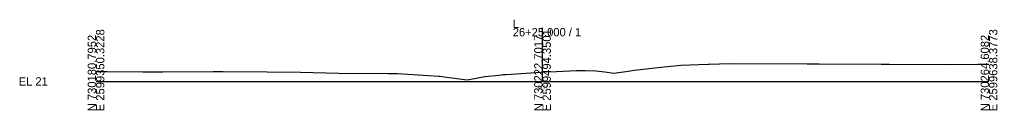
# Model space of a CAD drawing. Extents: x -26 to 3303, y -10 to 9555.
# Drawn here: x 2974.3 to 3302.8, y 2490.3 to 2520.7 of the extents above; entities that cross this region are included whole.
import ezdxf

# ---------------------------------------------------------------- set-up
doc = ezdxf.new("R2010")
doc.units = 0
for name, color, linetype in [('Exist Cross Section Cell', 7, 'Continuous'), ('Exist XS Center Line Elevation Label', 7, 'Continuous'), ('Exist XS Ground Line', 7, 'Continuous')]:
    doc.layers.add(name, color=color, linetype=linetype)

msp = doc.modelspace()

# ---------------------------------------------------------------- linework, layer by layer
at = {"layer": 'Exist Cross Section Cell'}
for p, q in [((3150, 2500), (3150, 2517.89)), ((3000, 2500), (3150, 2500)), ((3150, 2500), (3300, 2500))]:
    msp.add_line(p, q, dxfattribs=at)
at = {"layer": 'Exist XS Ground Line'}
msp.add_lwpolyline([(3000, 2503.34), (3001.67, 2503.34), (3003.21, 2503.34), (3003.76, 2503.34), (3015.68, 2503.19), (3022.48, 2503.2), (3039.39, 2503.38), (3042.73, 2503.35), (3057.49, 2503.18), (3068.71, 2503.06), (3081.52, 2502.72), (3098.03, 2502.66), (3101.31, 2502.6), (3115.13, 2501.79), (3115.64, 2501.74), (3117.01, 2501.52), (3124.69, 2500.52), (3125.41, 2500.65), (3130.65, 2501.61), (3135.47, 2502.15), (3136.75, 2502.3), (3137.8, 2502.36), (3149.43, 2503.14), (3150, 2503.17), (3154.69, 2503.37), (3161.45, 2503.7), (3164.37, 2503.63), (3167.96, 2503.57), (3170.9, 2503.2), (3173.93, 2502.75), (3179.52, 2503.6), (3180.8, 2503.76), (3189.76, 2504.72), (3196.48, 2505.42), (3205.54, 2505.8), (3205.97, 2505.82), (3212.9, 2505.95), (3238.87, 2505.9), (3242.89, 2505.88), (3263.74, 2505.8), (3265.27, 2505.82), (3266.55, 2505.83), (3285.78, 2505.7), (3296.23, 2505.73), (3300, 2505.76)], dxfattribs=at)

# ---------------------------------------------------------------- texts
at = {"layer": 'Exist Cross Section Cell'}
for s, p in [('L', (3140, 2517.89)), ('26+25.000 / 1', (3140, 2515.09)), ('EL 21', (2974, 2498.6))]:
    msp.add_text(s, height=2.8, dxfattribs=at).set_placement(p)
for s, p in [('E 2599350.3228', (3002.8, 2490)), ('E 2599494.3501', (3152.8, 2490)), ('E 2599638.3773', (3302.8, 2490)), ('N 730180.7952', (3000, 2490)), ('N 730222.7017', (3150, 2490)), ('N 730264.6082', (3300, 2490))]:
    msp.add_text(s, height=2.8, rotation=90, dxfattribs=at).set_placement(p)
at = {"layer": 'Exist XS Center Line Elevation Label'}
msp.add_text('24.17', height=1, dxfattribs=at).set_placement((3148.37, 2497.67))

doc.saveas('drawing.dxf')
